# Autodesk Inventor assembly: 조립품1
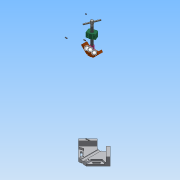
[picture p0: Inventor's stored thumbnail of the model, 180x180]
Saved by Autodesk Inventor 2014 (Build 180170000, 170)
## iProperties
Created: 2019-04
Part Number: 조립품1
Document SubType Name: Assembly
Designer: net
Author: net
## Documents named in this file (10)
- C:\Users\net\Desktop\490407V1035\조립품1.iam
- C:\Users\net\Desktop\490407V1035\부품1.ipt
- C:\Users\net\Desktop\490407V1035\멈춤나사 M4x5.ipt
- C:\Users\net\Desktop\490407V1035\멈춤나사 M4x10.ipt
- C:\Users\net\Desktop\490407V1035\평행 핀 2.5x24.ipt
- C:\Users\net\Desktop\490407V1035\핸들.ipt
- C:\Users\net\Desktop\490407V1035\조.ipt
- C:\Users\net\Desktop\490407V1035\리드스크류.ipt
- C:\Users\net\Desktop\490407V1035\부시.ipt
- C:\Users\net\Desktop\490407V1035\서포트.ipt
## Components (1 placed, 1 different names)
1. 핸들:1
